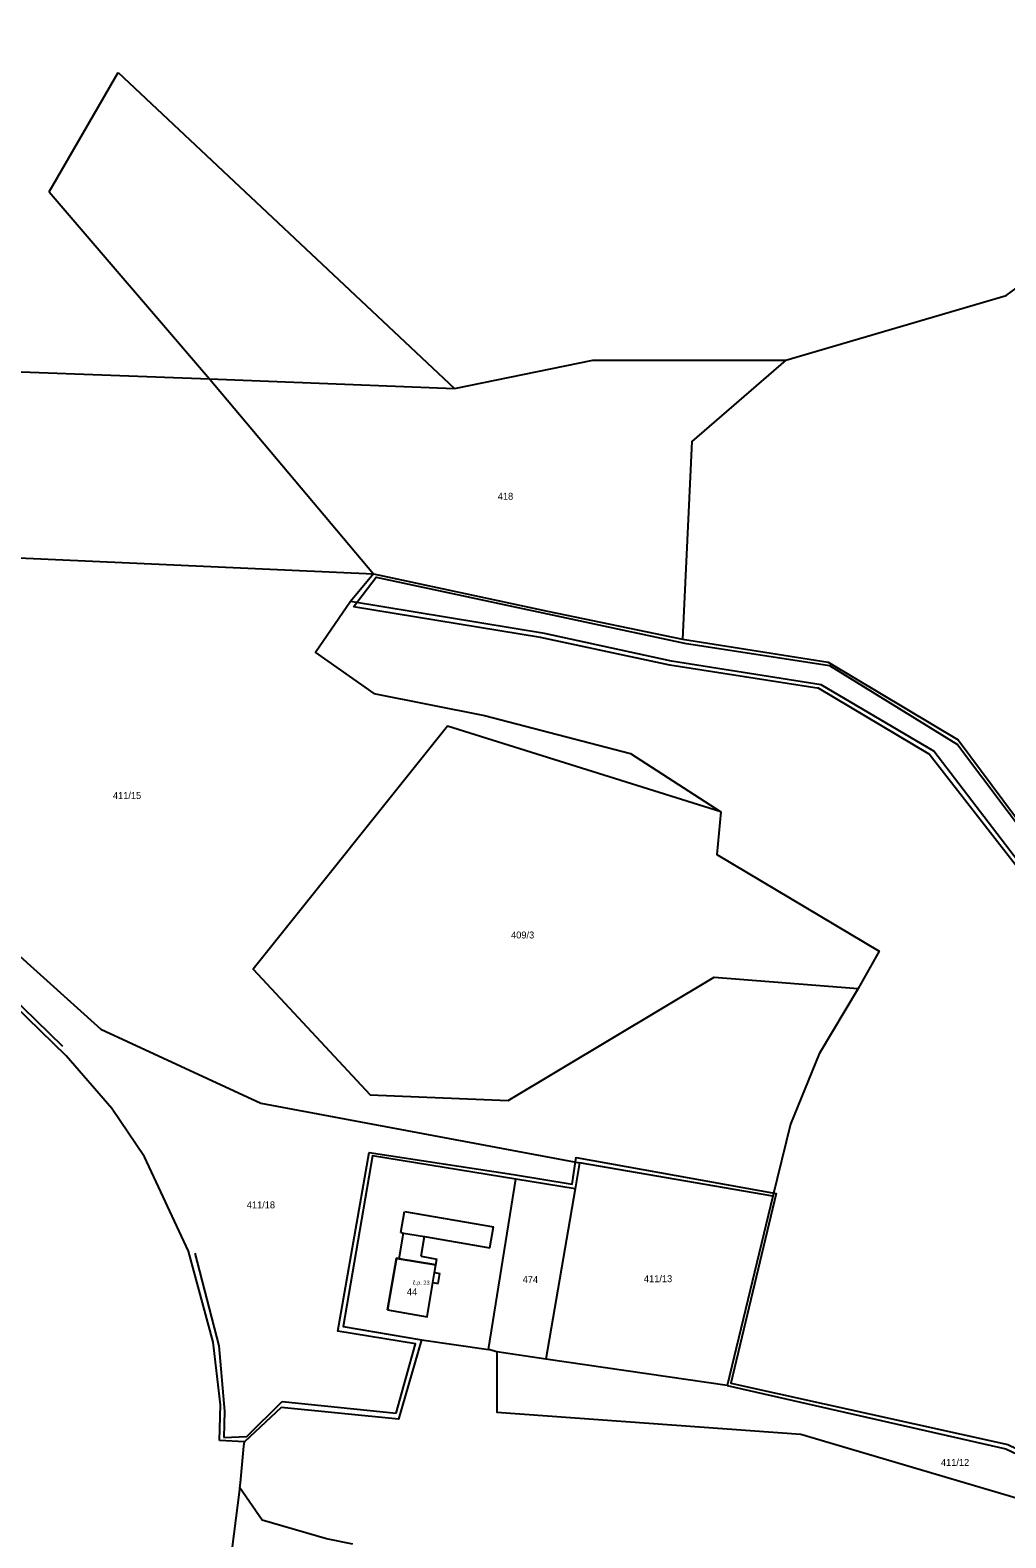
# Model space of a CAD drawing. Extents: x -880531 to -877616, y -1023932 to -1021350.
# Drawn here: x -880281.2 to -880041.3, y -1022593.9 to -1022223.5 of the extents above; entities that cross this region are included whole.
import ezdxf

# ---------------------------------------------------------------- set-up
doc = ezdxf.new("R2010")
doc.units = 0
for name, color, linetype in [('Definiční body', 7, 'Continuous'), ('Hranice parcel', 7, 'Continuous'), ('Parcelní čísla', 7, 'Continuous'), ('Polygon budovy', 7, 'Continuous'), ('Vnitřní kresba', 7, 'Continuous')]:
    doc.layers.add(name, color=color, linetype=linetype)

msp = doc.modelspace()

# ---------------------------------------------------------------- linework, layer by layer
at = {"layer": 'Hranice parcel'}
for p, q in [((-880285.88, -1022353.02), (-880196.77, -1022357.04)), ((-880196.77, -1022357.04), (-880202.4, -1022363.81)), ((-880146.12, -1022501.79), (-880147.2, -1022508.1)), ((-880098.6, -1022509.95), (-880146.12, -1022501.79)), ((-880168.5, -1022547.6), (-880161.8, -1022505.8)), ((-880147.2, -1022508.1), (-880161.8, -1022505.8)), ((-880147.2, -1022508.1), (-880154.4, -1022550)), ((-880098.6, -1022509.95), (-880109.86, -1022556.49)), ((-880185, -1022545.2), (-880168.5, -1022547.6)), ((-880166.5, -1022548.2), (-880168.5, -1022547.6)), ((-880154.4, -1022550), (-880166.5, -1022548.2)), ((-880109.86, -1022556.49), (-880154.4, -1022550)), ((-880228.52, -1022570.28), (-880234.6, -1022570)), ((-880229.65, -1022581.98), (-880229.6, -1022581.58))]:
    msp.add_line(p, q, dxfattribs=at)
for points in [[(-880095.42, -1022304.53), (-880041.25, -1022288.65), (-880003.96, -1022261.33)], [(-880293.53, -1022352.68), (-880307.71, -1022306.49), (-880237.11, -1022309.12), (-880176.85, -1022311.48)], [(-880176.85, -1022311.48), (-880142.9, -1022304.54), (-880095.42, -1022304.53)], [(-880095.42, -1022304.53), (-880118.55, -1022324.52), (-880120.79, -1022373.06)], [(-880196.77, -1022357.04), (-880154.03, -1022366.18), (-880120.79, -1022373.06)], [(-880202.4, -1022363.81), (-880211.01, -1022376.38), (-880196.68, -1022386.42), (-880169.5, -1022391.8), (-880133.65, -1022401.17), (-880111.39, -1022415.53)], [(-879927.95, -1022512.07), (-879968.07, -1022481.99), (-880006.9, -1022460.74), (-880027.04, -1022442.45), (-880059.05, -1022400.63), (-880086.76, -1022384.28), (-880123.5, -1022378.49), (-880154.72, -1022371.67), (-880202.4, -1022363.81)], [(-880120.79, -1022373.06), (-880085.05, -1022378.77), (-880053.08, -1022397.83), (-880022.5, -1022438.88), (-880002.99, -1022457.32), (-879965.63, -1022478.64), (-879926.96, -1022507.44)], [(-880111.39, -1022415.53), (-880178.56, -1022394.45), (-880226.32, -1022454.19), (-880197.63, -1022485.03), (-880163.68, -1022486.42), (-880113.04, -1022456.1), (-880077.64, -1022458.91)], [(-880234.6, -1022570), (-880234.38, -1022561.23), (-880236.2, -1022545.85), (-880242.27, -1022523.44), (-880253.08, -1022500.29), (-880261.13, -1022488.37), (-880272.31, -1022475.43), (-880300.95, -1022447.69), (-880335.48, -1022414.24)], [(-880111.39, -1022415.53), (-880112.37, -1022426.02), (-880072.49, -1022449.78), (-880077.64, -1022458.91)], [(-880308.75, -1022428.16), (-880285.32, -1022449.52), (-880263.77, -1022468.93), (-880224.44, -1022487.13), (-880146.12, -1022501.79)], [(-880077.64, -1022458.91), (-880087.27, -1022475), (-880094.31, -1022492.21), (-880098.6, -1022509.95)], [(-880161.8, -1022505.8), (-880197, -1022500), (-880204.2, -1022542), (-880185, -1022545.2)], [(-880185, -1022545.2), (-880190.6, -1022564.7), (-880219.5, -1022561.9), (-880228.52, -1022570.28)], [(-880166.5, -1022548.2), (-880166.5, -1022563), (-880091.71, -1022568.45), (-880004.96, -1022594.04), (-879942.81, -1022618.93)], [(-880109.86, -1022556.49), (-880041.33, -1022572.02), (-880004.82, -1022589.23), (-879971.92, -1022601.09), (-879941.5, -1022616.12)], [(-880229.6, -1022581.58), (-880229.48, -1022580.34), (-880228.62, -1022571.37), (-880228.52, -1022570.28)], [(-880275.46, -1022817.7), (-880256.82, -1022750.96), (-880251.78, -1022710.78), (-880245.5, -1022685.14), (-880239.72, -1022660.82), (-880229.65, -1022581.98)], [(-880201.85, -1022595.42), (-880208.37, -1022594.15), (-880224.11, -1022589.52), (-880229.6, -1022581.58)]]:
    msp.add_lwpolyline(points, dxfattribs=at)
at = {"layer": 'Polygon budovy'}
msp.add_lwpolyline([(-880193.32, -1022537.9), (-880183.63, -1022539.56), (-880182.2, -1022531.15), (-880181.78, -1022528.69), (-880181.46, -1022526.84), (-880190.48, -1022525.3), (-880191.14, -1022525.19)], close=True, dxfattribs=at)
at = {"layer": 'Vnitřní kresba'}
for p, q in [((-880276.48, -1022263.16), (-880259.54, -1022233.83)), ((-880259.54, -1022233.83), (-880176.85, -1022311.48)), ((-880276.48, -1022263.16), (-880237.11, -1022309.12)), ((-880237.11, -1022309.12), (-880196.77, -1022357.04)), ((-880303.63, -1022443.58), (-880273.2, -1022473.11)), ((-880190.06, -1022518.89), (-880189.18, -1022513.72)), ((-880189.18, -1022513.72), (-880167.28, -1022517.48)), ((-880168.18, -1022522.63), (-880167.28, -1022517.48)), ((-880190.48, -1022525.3), (-880189.43, -1022519)), ((-880190.06, -1022518.89), (-880189.43, -1022519)), ((-880189.43, -1022519), (-880184.28, -1022519.88)), ((-880185.1, -1022524.69), (-880184.28, -1022519.88)), ((-880184.28, -1022519.88), (-880168.18, -1022522.63)), ((-880240.72, -1022523.95), (-880234.84, -1022546.73)), ((-880193.32, -1022537.9), (-880191.14, -1022525.19)), ((-880191.14, -1022525.19), (-880190.48, -1022525.3)), ((-880190.48, -1022525.3), (-880181.46, -1022526.84)), ((-880185.1, -1022524.69), (-880181.21, -1022525.39)), ((-880181.46, -1022526.84), (-880181.21, -1022525.39)), ((-880182.2, -1022531.15), (-880181.78, -1022528.69)), ((-880181.78, -1022528.69), (-880181.46, -1022526.84)), ((-880181.78, -1022528.69), (-880180.5, -1022528.9)), ((-880180.92, -1022531.37), (-880180.5, -1022528.9)), ((-880183.63, -1022539.56), (-880182.2, -1022531.15)), ((-880182.2, -1022531.15), (-880180.92, -1022531.37)), ((-880193.32, -1022537.9), (-880183.63, -1022539.56)), ((-880234.84, -1022546.73), (-880233.42, -1022562.73)), ((-880227.93, -1022568.96), (-880219.25, -1022560.35)), ((-880219.25, -1022560.35), (-880191.2, -1022563.28)), ((-880233.42, -1022562.73), (-880233.59, -1022569.21)), ((-880233.59, -1022569.21), (-880227.93, -1022568.96))]:
    msp.add_line(p, q, dxfattribs=at)
for points in [[(-880201.71, -1022365.15), (-880196.14, -1022357.83), (-880120.3, -1022374.06), (-880084.72, -1022379.56), (-880053.24, -1022398.97), (-880022.87, -1022439.38), (-880003.47, -1022457.83), (-879966.2, -1022479.16), (-879926.77, -1022508.59), (-879901.81, -1022484.25), (-879922.79, -1022426.66), (-879933.03, -1022374.74), (-879949.86, -1022331.15), (-879965.49, -1022317.02), (-879964.96, -1022306.01), (-880003.12, -1022261.31), (-879998.66, -1022243.17), (-879984.04, -1022271.49), (-879972.27, -1022258.28), (-879982.45, -1022223.45), (-879946.03, -1022233.94)], [(-880087.25, -1022385.24), (-880123.94, -1022379.51), (-880155.74, -1022372.67), (-880201.71, -1022365.15)], [(-879920.52, -1022591.58), (-879921.27, -1022592.36), (-879940.51, -1022582.5), (-879942.89, -1022575.18), (-879927.15, -1022532.55), (-879925.56, -1022523.32), (-879929.38, -1022511.55), (-879968.48, -1022482.85), (-880008.23, -1022461.06), (-880027.79, -1022442.92), (-880060.18, -1022401.31), (-880087.53, -1022385.08)], [(-880191.2, -1022563.28), (-880186.43, -1022546.26), (-880205.51, -1022543.08), (-880197.88, -1022499.18), (-880162.39, -1022504.64), (-880147.92, -1022507.02), (-880146.97, -1022500.34)], [(-880146.98, -1022500.44), (-880097.84, -1022509.25), (-880108.97, -1022555.86), (-880040.89, -1022570.99), (-880004.48, -1022588.49), (-879972.36, -1022599.94)]]:
    msp.add_lwpolyline(points, dxfattribs=at)

# ---------------------------------------------------------------- texts
at = {"layer": 'Definiční body'}
msp.add_text('č.p. 23', height=1, dxfattribs=at).set_placement((-880187.13, -1022531.69))
at = {"layer": 'Parcelní čísla'}
for s, p in [('418', (-880166.24, -1022338.83)), ('411/15', (-880260.835, -1022412.35)), ('409/3', (-880162.97, -1022446.62)), ('411/18', (-880227.937, -1022512.94)), ('44', (-880188.58, -1022534.29)), ('474', (-880160.12, -1022531.26)), ('411/13', (-880130.31, -1022531.07)), ('411/12', (-880057.31, -1022576.21))]:
    msp.add_text(s, height=1.7, dxfattribs=at).set_placement(p)

doc.saveas('drawing.dxf')
